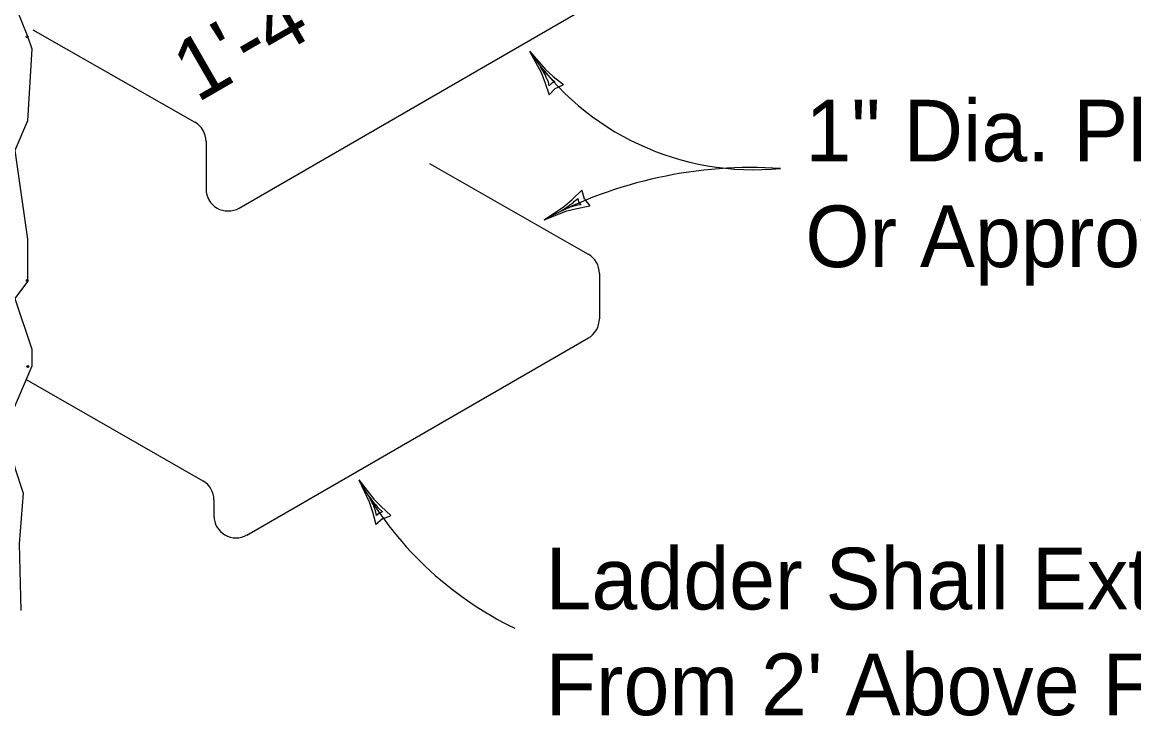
# Model space of a CAD drawing. Extents: x -7.1 to 10, y -5 to 6.
# Drawn here: x 3.017 to 4.208, y 2.762 to 3.525 of the extents above; entities that cross this region are included whole.
import ezdxf

# ---------------------------------------------------------------- set-up
doc = ezdxf.new("R2010")
doc.units = 0
for name, color, linetype in [('Level 4', 7, 'Continuous'), ('Level 5', 7, 'Continuous'), ('Level 6', 7, 'Continuous'), ('Level 7', 7, 'Continuous')]:
    doc.layers.add(name, color=color, linetype=linetype)

msp = doc.modelspace()

# ---------------------------------------------------------------- linework, layer by layer
at = {"layer": 'Level 4'}
for p, q in [((3.2494, 3.3255), (3.6166, 3.5375)), ((3.0285, 3.5167), (3.2021, 3.4174)), ((3.214, 3.3969), (3.214, 3.3459)), ((3.4536, 3.3731), (3.6236, 3.2759)), ((3.6355, 3.2554), (3.6355, 3.2066)), ((3.2579, 2.9749), (3.6237, 3.1862)), ((3.0211, 3.1415), (3.2106, 3.0331)), ((3.2225, 3.0126), (3.2225, 2.9954))]:
    msp.add_line(p, q, dxfattribs=at)
msp.add_lwpolyline([(3.0129, 3.6767), (3.0182, 3.6185), (3.0137, 3.5868), (3.0046, 3.555), (3.0227, 3.5097), (3.0273, 3.4961), (3.0227, 3.419), (3.0091, 3.3872), (3.0227, 3.292), (3.0227, 3.2466), (3.0091, 3.2285), (3.0273, 3.174), (3.0273, 3.1559), (3.0001, 3.0924), (3.0091, 3.047), (3.0182, 3.0198), (3.0137, 2.9654), (3.0156, 2.8939)], dxfattribs=at)
for centre, start, end in [((3.1904, 3.3969), 0, 60.2339), ((3.2376, 3.3459), 180, 300.0037), ((3.6119, 3.2554), 0, 60.2343), ((3.6119, 3.2066), 300.0053, 360), ((3.1989, 3.0126), 0, 60.2363), ((3.2461, 2.9954), 180, 300.0046)]:
    msp.add_arc(centre, 0.0236, start, end, dxfattribs=at)
at = {"layer": 'Level 5'}
msp.add_line((3.0228, 3.1559), (3.0228, 3.1545), dxfattribs=at)
for centre in [(3.0222, 3.509), (3.0222, 3.2479), (3.0231, 3.1557)]:
    msp.add_circle(centre, 0.00105, dxfattribs=at)
at = {"layer": 'Level 7'}
for p, q in [((3.5882, 3.4538), (3.5966, 3.4574)), ((3.5882, 3.4538), (3.5817, 3.447)), ((3.6195, 3.335), (3.617, 3.3439)), ((3.6195, 3.335), (3.6253, 3.3278)), ((3.403, 2.9924), (3.3961, 2.9861)), ((3.403, 2.9924), (3.4117, 2.9956))]:
    msp.add_line(p, q, dxfattribs=at)
for points in [[(3.5605, 3.4937), (3.573, 3.4708), (3.5771, 3.4603), (3.5817, 3.447)], [(3.5605, 3.4937), (3.5777, 3.4741), (3.5861, 3.4666), (3.5972, 3.4578)], [(3.5723, 3.4768), (3.5767, 3.4715), (3.5799, 3.4684), (3.5823, 3.4657), (3.5846, 3.4638), (3.5878, 3.4609), (3.5844, 3.4595), (3.5817, 3.4566), (3.5809, 3.4603), (3.5799, 3.4628), (3.5786, 3.4653), (3.5776, 3.4678), (3.5763, 3.4699), (3.575, 3.4725), (3.5723, 3.4768)], [(3.5762, 3.313), (3.598, 3.3273), (3.6065, 3.3347), (3.6167, 3.3445)], [(3.5946, 3.3224), (3.6004, 3.3261), (3.6038, 3.3288), (3.6069, 3.3308), (3.609, 3.3328), (3.6124, 3.3357), (3.6133, 3.3321), (3.6158, 3.329), (3.6121, 3.3287), (3.6095, 3.328), (3.6068, 3.3271), (3.6042, 3.3264), (3.6019, 3.3255), (3.5992, 3.3245), (3.5946, 3.3224)], [(3.5762, 3.313), (3.6006, 3.3223), (3.6115, 3.325), (3.6253, 3.3278)], [(3.3778, 3.034), (3.3889, 3.0104), (3.3923, 2.9997), (3.3961, 2.9861)], [(3.3778, 3.034), (3.3937, 3.0134), (3.4017, 3.0054), (3.4122, 2.9959)], [(3.3886, 3.0164), (3.3927, 3.0108), (3.3956, 3.0076), (3.3978, 3.0047), (3.4, 3.0027), (3.4031, 2.9996), (3.3996, 2.9984), (3.3967, 2.9957), (3.3961, 2.9994), (3.3953, 3.002), (3.3941, 3.0046), (3.3933, 3.0071), (3.3922, 3.0093), (3.391, 3.012), (3.3886, 3.0164)]]:
    msp.add_lwpolyline(points, dxfattribs=at)
for centre, radius, start, end in [((3.8008, 3.6572), 0.2907, 214.2369, 275.6847), ((3.7993, 2.8963), 0.4726, 86.3229, 118.1676), ((3.71, 3.2154), 0.3784, 208.639, 244.1238)]:
    msp.add_arc(centre, radius, start, end, dxfattribs=at)

# ---------------------------------------------------------------- texts
at = {"layer": 'Level 6'}
msp.add_text('1\'-4"', height=0.06613, rotation=30.0006, dxfattribs=at).set_placement((3.2044, 3.4378))
for s, p in [('1" Dia. Plain Bars', (3.8562, 3.3754)), ('Or Approved Alternate', (3.8562, 3.2621)), ('Ladder Shall Extend', (3.5779, 2.8951)), ("From 2' Above Floor Up", (3.5779, 2.7817))]:
    msp.add_text(s, height=0.066125, dxfattribs=at).set_placement(p)

doc.saveas('drawing.dxf')
